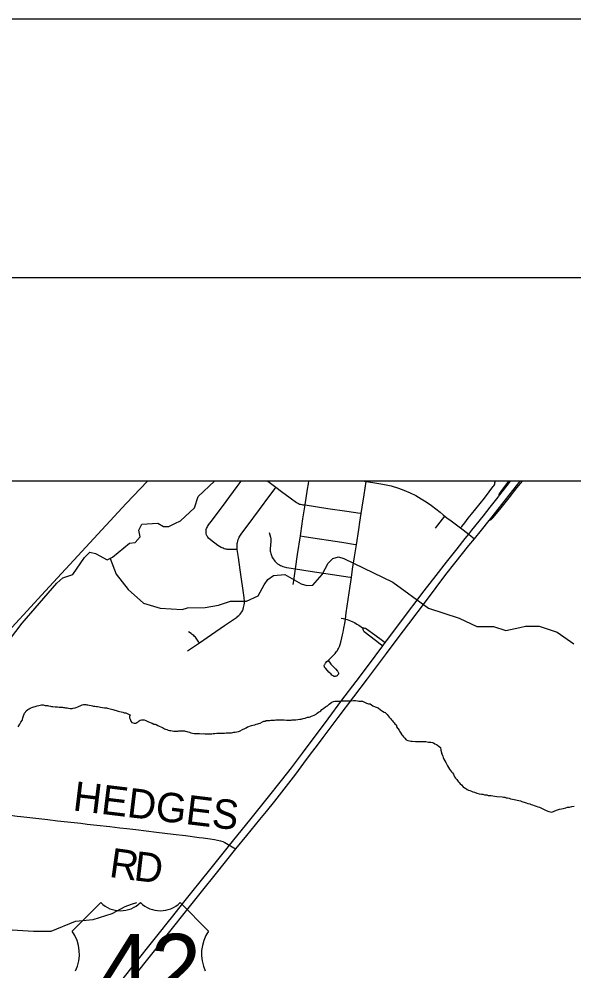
# Model space of a CAD drawing. Extents: x 0 to 34, y 0 to 22.
# Drawn here: x 11.27 to 12.342, y 20.159 to 22 of the extents above; entities that cross this region are included whole.
import ezdxf

# ---------------------------------------------------------------- set-up
doc = ezdxf.new("R2010")
doc.units = 0
for name, color, linetype in [('GM_X_City_Street', 7, 'Continuous'), ('GM_X_Corporation', 7, 'Continuous'), ('GM_X_Interchange_Ramps', 7, 'Continuous'), ('GM_X_Minor_River', 7, 'Continuous'), ('GM_X_Rail_Line', 7, 'Continuous'), ('GM_X_Township_Road', 7, 'Continuous'), ('GM_X_Township_Road_Text', 7, 'Continuous'), ('GM_X_US_Location', 7, 'Continuous'), ('GM_X_US_Route', 7, 'Continuous'), ('GM_X_US_Shield', 7, 'Continuous'), ('SH_Border', 7, 'Continuous'), ('SH_Cut_Line', 7, 'Continuous')]:
    doc.layers.add(name, color=color, linetype=linetype)

msp = doc.modelspace()

# ---------------------------------------------------------------- linework, layer by layer
at = {"layer": 'GM_X_City_Street'}
msp.add_line((12.0744, 21.0153), (12.0926, 21.0386), dxfattribs=at)
for points in [[(11.6914, 20.974), (11.6889, 20.974), (11.6833, 20.9739), (11.6754, 20.9738), (11.672, 20.9741), (11.6706, 20.9743), (11.6684, 20.9747), (11.6662, 20.9753), (11.6641, 20.9762), (11.6622, 20.977), (11.6602, 20.9779), (11.6573, 20.9795), (11.6538, 20.9816), (11.6395, 20.9925), (11.6358, 20.9959), (11.6345, 20.9974), (11.6336, 20.9988), (11.6328, 21.0003), (11.6319, 21.0022), (11.6314, 21.0046), (11.6312, 21.0065), (11.6311, 21.0083), (11.6313, 21.0104), (11.6315, 21.0126), (11.6321, 21.0147), (11.6329, 21.0165), (11.6338, 21.0182), (11.6354, 21.0206), (11.6379, 21.0241), (11.6416, 21.0288), (11.6699, 21.0665), (11.6913, 21.0955), (11.6991, 21.1059)], [(11.7505, 21.1059), (11.7555, 21.1021), (11.7661, 21.0942), (11.7769, 21.0861), (11.7935, 21.0741), (11.8061, 21.0648), (11.8082, 21.0636), (11.81, 21.0626), (11.812, 21.0618), (11.8139, 21.0613), (11.8164, 21.0609), (11.8183, 21.0605), (11.8225, 21.06), (11.8663, 21.0534), (11.9033, 21.0477), (11.9289, 21.0441), (11.9311, 21.0438)], [(11.7994, 20.9064), (11.7999, 20.9095), (11.8038, 20.9365), (11.8078, 20.9641), (11.8134, 21), (11.8141, 21.0046), (11.8184, 21.0329), (11.8225, 21.06), (11.8272, 21.0905), (11.8288, 21.101), (11.8299, 21.1059)], [(11.8668, 20.7591), (11.8695, 20.7558), (11.8725, 20.7523), (11.8811, 20.7433), (11.8851, 20.7385), (11.8858, 20.7375), (11.8864, 20.7364), (11.8868, 20.7355), (11.887, 20.7347), (11.8871, 20.7338), (11.8869, 20.7329), (11.8866, 20.7321), (11.8861, 20.7313), (11.8853, 20.7305), (11.8842, 20.7297), (11.883, 20.7291), (11.8819, 20.7287), (11.8808, 20.7284), (11.8798, 20.7284), (11.879, 20.7285), (11.8782, 20.7286), (11.8773, 20.729), (11.8765, 20.7294), (11.8755, 20.7301), (11.8745, 20.7309), (11.8728, 20.7326), (11.8686, 20.7368), (11.8656, 20.7397), (11.8619, 20.744), (11.8608, 20.7453), (11.8601, 20.7464), (11.8598, 20.7475), (11.8596, 20.7484), (11.8596, 20.7495), (11.8598, 20.7505), (11.8604, 20.7517), (11.861, 20.7527), (11.8617, 20.7538), (11.8647, 20.757), (11.8668, 20.7591), (11.8713, 20.7636), (11.8805, 20.7728), (11.8834, 20.7765), (11.885, 20.7787), (11.886, 20.7805), (11.887, 20.7826), (11.8887, 20.7865), (11.89, 20.7904), (11.8915, 20.7949), (11.8937, 20.8032), (11.895, 20.8088), (11.8962, 20.814), (11.8975, 20.8215), (11.8991, 20.8306), (11.9003, 20.8392), (11.9021, 20.8515), (11.9095, 20.9031), (11.9119, 20.9198), (11.9142, 20.9357), (11.9183, 20.9595), (11.9219, 20.9829), (11.9264, 21.0124), (11.9285, 21.0266), (11.9311, 21.0438), (11.9329, 21.056), (11.9365, 21.0799), (11.9403, 21.1055), (11.9404, 21.1059)], [(11.9372, 21.1059), (11.9403, 21.1055), (11.9532, 21.1036), (11.9728, 21.1003), (11.9892, 21.0967), (12.0028, 21.0927), (12.0133, 21.0888), (12.0253, 21.0836), (12.0364, 21.078), (12.0472, 21.0719), (12.0568, 21.0661), (12.0668, 21.0588), (12.0835, 21.0458), (12.0893, 21.0412), (12.0926, 21.0386), (12.0968, 21.0353), (12.1049, 21.029), (12.123, 21.0155)], [(11.5954, 20.7778), (11.6183, 20.7935), (11.6333, 20.8038), (11.6667, 20.8266), (11.6879, 20.8408), (11.6903, 20.8426), (11.6927, 20.8446), (11.6945, 20.8461), (11.6967, 20.8486), (11.6983, 20.8506), (11.7, 20.8531), (11.7012, 20.8551), (11.7026, 20.8582), (11.7037, 20.8616), (11.7044, 20.8643), (11.7049, 20.867), (11.7051, 20.8701), (11.7053, 20.8732), (11.7046, 20.8813), (11.6972, 20.9348), (11.6939, 20.9582), (11.6914, 20.974), (11.6909, 20.9804), (11.6909, 20.9827), (11.6912, 20.9854), (11.6917, 20.9876), (11.6923, 20.9902), (11.6932, 20.9932), (11.6942, 20.9955), (11.6952, 20.9979), (11.6964, 20.9999), (11.7001, 21.0056), (11.7104, 21.0193), (11.7341, 21.0513), (11.7546, 21.0786), (11.7645, 21.0921), (11.7661, 21.0942)], [(11.753, 21.0067), (11.7557, 20.9978), (11.7563, 20.9948), (11.7566, 20.9925), (11.7566, 20.9901), (11.7554, 20.9816), (11.7549, 20.9759), (11.755, 20.9736), (11.7552, 20.9708), (11.7556, 20.9685), (11.7561, 20.9664), (11.7567, 20.9643), (11.7575, 20.9622), (11.7585, 20.9598), (11.7598, 20.9576), (11.761, 20.9555), (11.7626, 20.9533), (11.7641, 20.9514), (11.7659, 20.9495), (11.7673, 20.948), (11.7692, 20.9464), (11.7707, 20.9452), (11.7729, 20.944), (11.7747, 20.9429), (11.7769, 20.942), (11.7794, 20.9411), (11.7823, 20.9402), (11.7866, 20.9392), (11.7909, 20.9384), (11.8038, 20.9365), (11.8321, 20.9321), (11.8623, 20.9277), (11.9096, 20.9202), (11.9119, 20.9198)], [(11.8134, 21), (11.821, 20.9988), (11.8504, 20.9944), (11.8675, 20.9918), (11.8933, 20.9879), (11.92, 20.9833), (11.9219, 20.9829)], [(11.8924, 20.8412), (11.8961, 20.8403), (11.9003, 20.8392), (11.9039, 20.8383), (11.9068, 20.8373), (11.9104, 20.8359), (11.9148, 20.8341), (11.918, 20.8324), (11.9226, 20.8296), (11.9261, 20.8273), (11.9334, 20.8224)], [(11.6183, 20.7935), (11.6174, 20.7948), (11.6132, 20.8007), (11.6118, 20.8024), (11.6105, 20.8042), (11.6089, 20.8058), (11.6073, 20.8074), (11.6044, 20.8095), (11.6023, 20.8112), (11.597, 20.8143)], [(11.9334, 20.8224), (11.9341, 20.8198), (11.9347, 20.8179), (11.9356, 20.8164), (11.9366, 20.8151), (11.9586, 20.7987), (11.9677, 20.7915), (11.9729, 20.7874)], [(11.9334, 20.8224), (11.9356, 20.8222), (11.9371, 20.822), (11.9392, 20.8214), (11.9412, 20.8205), (11.9571, 20.8086), (11.9721, 20.7976), (11.9776, 20.7937)]]:
    msp.add_lwpolyline(points, dxfattribs=at)
at = {"layer": 'GM_X_Corporation'}
msp.add_lwpolyline([(16.3375, 14.3932), (16.3375, 21.1059), (9.5375, 21.1059), (9.5375, 15.0426), (9.5452, 15.0418), (9.7185, 15.0258), (10.2502, 14.9799), (10.3112, 14.9746), (10.787, 14.9212), (11.3129, 14.8754), (11.3292, 14.8742), (12.1361, 14.7923), (13.6754, 14.6095), (14.714, 14.5341), (15.778, 14.4476), (16.0263, 14.4243)], close=True, dxfattribs=at)
msp.add_lwpolyline([(16.3375, 21.1059), (10.7333, 21.1059), (10.7324, 21.0977), (10.6961, 20.747), (10.69, 20.684), (10.7047, 20.6667), (10.7316, 20.6353), (10.7568, 20.6059), (10.7799, 20.5791), (10.8028, 20.5521), (10.8263, 20.5244), (10.8351, 20.5143), (10.841, 20.5074), (10.8449, 20.5034), (10.8495, 20.499), (10.8527, 20.4964), (10.8546, 20.4951), (10.8943, 20.447), (11.3101, 19.9435)], dxfattribs=at)
at = {"layer": 'GM_X_Interchange_Ramps'}
for points in [[(12.1783, 21.0301), (12.1807, 21.0313), (12.1821, 21.032), (12.1838, 21.0334), (12.1856, 21.0352), (12.1989, 21.0514), (12.2169, 21.0738), (12.2321, 21.093), (12.2425, 21.1059)], [(12.2159, 21.1059), (12.2008, 21.086), (12.1979, 21.0817), (12.197, 21.0797), (12.1967, 21.0784), (12.1963, 21.0762)]]:
    msp.add_lwpolyline(points, dxfattribs=at)
at = {"layer": 'GM_X_Minor_River'}
for points in [[(11.2514, 20.7988), (11.2759, 20.8311), (11.3425, 20.9089), (11.3544, 20.9193), (11.3735, 20.9255), (11.3961, 20.9585), (11.4062, 20.9686), (11.4175, 20.9661), (11.4397, 20.954), (11.4504, 20.9591), (11.4832, 20.9859), (11.4938, 20.9876), (11.5035, 20.9984), (11.5014, 21.011), (11.507, 21.0227), (11.5377, 21.0248), (11.5486, 21.0182), (11.5593, 21.0184), (11.5704, 21.0239), (11.5815, 21.029), (11.6089, 21.0547), (11.6161, 21.0766), (11.6476, 21.1059)], [(11.4455, 20.9567), (11.4571, 20.9259), (11.4805, 20.8967), (11.5104, 20.87), (11.5422, 20.8603), (11.585, 20.858), (11.5949, 20.8613), (11.6291, 20.8618), (11.655, 20.866), (11.6783, 20.8739), (11.7095, 20.8741), (11.7316, 20.884), (11.7434, 20.9058), (11.7504, 20.9156), (11.7612, 20.9238), (11.7836, 20.9253), (11.8152, 20.9073), (11.8258, 20.9041), (11.8372, 20.905), (11.8558, 20.9252), (11.8668, 20.9474), (11.8764, 20.9564), (11.8871, 20.9596), (11.8973, 20.9564), (11.9918, 20.9107), (12.0608, 20.8605), (12.1205, 20.8409), (12.1544, 20.8248), (12.1866, 20.8246), (12.2104, 20.817), (12.2379, 20.8229), (12.2486, 20.8254), (12.2747, 20.8254), (12.3099, 20.8137), (12.3418, 20.7912)], [(11.6019, 20.6194), (11.6083, 20.6178), (11.6118, 20.6178), (11.6148, 20.6177), (11.6167, 20.6177), (11.6186, 20.6177), (11.6227, 20.6173), (11.6258, 20.6177), (11.6288, 20.6172), (11.6326, 20.6172), (11.6356, 20.6172), (11.6375, 20.6172), (11.6398, 20.6172), (11.6421, 20.6171), (11.6447, 20.6179), (11.6481, 20.6182), (11.6516, 20.6186), (11.6554, 20.6185), (11.658, 20.6185), (11.6607, 20.6185), (11.6633, 20.6185), (11.6667, 20.6188), (11.6698, 20.6195), (11.6717, 20.6195), (11.6736, 20.6195), (11.6766, 20.6195), (11.68, 20.6195), (11.683, 20.6198), (11.6849, 20.6202), (11.6876, 20.6202), (11.6906, 20.6209), (11.694, 20.6216), (11.6959, 20.6224), (11.7028, 20.6261), (11.7047, 20.6268), (11.7085, 20.6291), (11.7112, 20.6306), (11.7138, 20.6317), (11.7169, 20.6328), (11.7188, 20.6332), (11.7218, 20.6343), (11.7256, 20.635), (11.7279, 20.6357), (11.7309, 20.6365), (11.7332, 20.6372), (11.7359, 20.6376), (11.7401, 20.6402), (11.7427, 20.6417), (11.7454, 20.642), (11.7473, 20.6428), (11.7499, 20.6428), (11.7537, 20.6431), (11.756, 20.6435), (11.7587, 20.6434), (11.7617, 20.6434), (11.7636, 20.6438), (11.7662, 20.6441), (11.7685, 20.6441), (11.7712, 20.6445), (11.7731, 20.6445), (11.775, 20.6441), (11.7772, 20.6444), (11.7799, 20.6444), (11.7822, 20.6444), (11.7867, 20.644), (11.7886, 20.6439), (11.792, 20.6439), (11.7958, 20.6439), (11.7977, 20.6442), (11.8007, 20.6442), (11.8045, 20.6446), (11.8087, 20.6449), (11.8125, 20.6456), (11.8148, 20.6456), (11.8186, 20.6467), (11.8224, 20.6478), (11.8269, 20.6493), (11.8303, 20.6497), (11.8326, 20.6504), (11.8349, 20.6515), (11.8368, 20.6519), (11.8398, 20.6534), (11.8437, 20.6556), (11.8456, 20.6575), (11.8486, 20.6594), (11.8509, 20.6605), (11.8532, 20.662), (11.8551, 20.6646), (11.8589, 20.6672), (11.862, 20.6695), (11.8639, 20.6706), (11.8661, 20.6717), (11.8692, 20.6747), (11.8719, 20.6766), (11.8745, 20.6785), (11.8772, 20.68), (11.8799, 20.6803), (11.8833, 20.6803), (11.8859, 20.6807), (11.8878, 20.6803), (11.8909, 20.6803)], [(11.8909, 20.6803), (11.8939, 20.681), (11.8965, 20.681), (11.8988, 20.6813), (11.9015, 20.6809), (11.906, 20.6813), (11.9117, 20.6812), (11.9163, 20.6815), (11.9197, 20.6815), (11.9235, 20.6811), (11.9261, 20.6807), (11.9299, 20.6803), (11.9333, 20.6803), (11.9412, 20.6768), (11.945, 20.6756), (11.9484, 20.6752), (11.9537, 20.6717), (11.9579, 20.6694), (11.9616, 20.6683), (11.9639, 20.6679), (11.968, 20.6636), (11.9722, 20.661), (11.9752, 20.659), (11.9771, 20.6583), (11.9794, 20.6563), (11.9809, 20.6544), (11.9831, 20.6521), (11.985, 20.6495), (11.9876, 20.6472), (11.9895, 20.6445), (11.9914, 20.6422), (11.9929, 20.6403), (11.9944, 20.6384), (11.9963, 20.6365), (11.9989, 20.6338), (11.9989, 20.6311), (12.0015, 20.6273), (12.0041, 20.6246), (12.0052, 20.6223), (12.0075, 20.6185), (12.0097, 20.6155), (12.0116, 20.6132), (12.0127, 20.6113), (12.015, 20.609), (12.018, 20.6059), (12.021, 20.6047), (12.0244, 20.6036), (12.0271, 20.6032), (12.0297, 20.6028), (12.0362, 20.6027), (12.0392, 20.6023), (12.0426, 20.6027), (12.0445, 20.6023), (12.0475, 20.6026), (12.0498, 20.6026), (12.0532, 20.6022), (12.0559, 20.6022), (12.0585, 20.6018), (12.0608, 20.6014), (12.0634, 20.6013), (12.0657, 20.6009), (12.0687, 20.6005), (12.071, 20.5998), (12.0736, 20.5982), (12.0763, 20.5967), (12.0785, 20.5951), (12.0816, 20.5928), (12.0842, 20.5909), (12.0849, 20.586), (12.086, 20.5814), (12.0864, 20.5795), (12.0875, 20.5772), (12.0886, 20.5738), (12.0894, 20.5715), (12.0908, 20.5681), (12.0946, 20.5616), (12.0964, 20.5582), (12.0976, 20.5555), (12.0998, 20.5524), (12.1017, 20.549), (12.1039, 20.5463), (12.1058, 20.5437), (12.1073, 20.5418), (12.1092, 20.5395), (12.1099, 20.5376), (12.1114, 20.5341), (12.1133, 20.5318), (12.1159, 20.5292), (12.1174, 20.5269), (12.1185, 20.525), (12.1204, 20.523), (12.1223, 20.5207), (12.1249, 20.5185), (12.1279, 20.5146), (12.1306, 20.5127), (12.1325, 20.5123), (12.1355, 20.5096), (12.1385, 20.5085), (12.1408, 20.5077), (12.1442, 20.5065), (12.1468, 20.5054)], [(11.2681, 20.631), (11.2708, 20.6363), (11.2731, 20.6401), (11.2754, 20.6431), (11.2765, 20.645), (11.2769, 20.648), (11.2785, 20.6518), (11.2796, 20.6552), (11.2804, 20.6571), (11.282, 20.659), (11.2831, 20.6616), (11.2865, 20.6646), (11.2892, 20.6657), (11.2911, 20.6672), (11.2942, 20.6683), (11.298, 20.6698), (11.301, 20.6702), (11.3044, 20.6717), (11.3078, 20.6724), (11.3105, 20.6728), (11.3131, 20.6731), (11.3162, 20.6731), (11.32, 20.6723), (11.3222, 20.6723), (11.3245, 20.6719), (11.3268, 20.6715), (11.3306, 20.6707), (11.3325, 20.6703), (11.3347, 20.6699), (11.3393, 20.6698), (11.3419, 20.6694), (11.3438, 20.6694), (11.3472, 20.669)], [(11.3472, 20.669), (11.3495, 20.6686), (11.3514, 20.6686), (11.3533, 20.6686), (11.3552, 20.6682), (11.3575, 20.6682), (11.3593, 20.6678), (11.3624, 20.6674), (11.365, 20.667), (11.3684, 20.6666), (11.3703, 20.6665), (11.3722, 20.6665), (11.3745, 20.6669), (11.3779, 20.6676), (11.3802, 20.6684), (11.3832, 20.6698), (11.3859, 20.671), (11.3878, 20.6713), (11.3916, 20.6736), (11.3939, 20.6739), (11.3958, 20.6743), (11.3988, 20.6739), (11.4007, 20.6735), (11.4026, 20.6731), (11.4052, 20.6727), (11.4087, 20.6723), (11.4113, 20.6715), (11.4136, 20.6711), (11.4162, 20.6707), (11.4193, 20.6703), (11.4215, 20.6699), (11.4242, 20.6695), (11.4272, 20.6691), (11.4348, 20.6679), (11.4367, 20.6679), (11.4386, 20.6675), (11.4408, 20.6671), (11.4431, 20.6663), (11.4457, 20.6655), (11.4484, 20.6647), (11.451, 20.6643), (11.4529, 20.6639), (11.4548, 20.6632), (11.4575, 20.6624), (11.4594, 20.662), (11.4613, 20.6612), (11.4635, 20.6608), (11.4669, 20.66), (11.4703, 20.6592), (11.473, 20.6581), (11.476, 20.6577), (11.4783, 20.6565), (11.4813, 20.6553), (11.4843, 20.6542), (11.4832, 20.6519), (11.4831, 20.6485), (11.4843, 20.6458), (11.4857, 20.642), (11.4876, 20.6393), (11.4918, 20.6378), (11.4937, 20.6378), (11.4956, 20.6378), (11.4975, 20.6393), (11.4998, 20.6408), (11.5017, 20.6423), (11.5036, 20.6434), (11.5066, 20.6441), (11.5093, 20.6445), (11.5115, 20.6444), (11.5149, 20.6429), (11.5187, 20.6413), (11.5229, 20.6394), (11.527, 20.6379), (11.53, 20.6363), (11.5327, 20.6359), (11.5346, 20.6351), (11.5376, 20.6336), (11.5402, 20.6324), (11.5467, 20.6297), (11.5485, 20.6282), (11.5508, 20.627), (11.5527, 20.6263), (11.5553, 20.6255), (11.5576, 20.6243), (11.5603, 20.6239), (11.5629, 20.6235), (11.5656, 20.6231), (11.5686, 20.6223), (11.5712, 20.6223), (11.5735, 20.6223), (11.5762, 20.6223), (11.5784, 20.623), (11.5811, 20.623), (11.5841, 20.6229), (11.5868, 20.6229), (11.5891, 20.6229), (11.5909, 20.6225), (11.5936, 20.6221), (11.5959, 20.6209), (11.5993, 20.6202), (11.6019, 20.6194)], [(12.1468, 20.5054), (12.1498, 20.5046), (12.1547, 20.5026), (12.1593, 20.5015), (12.1634, 20.5007), (12.1661, 20.5003), (12.1691, 20.4995), (12.1714, 20.4994), (12.1737, 20.4991), (12.1763, 20.4983), (12.1793, 20.4979), (12.1824, 20.4978), (12.1854, 20.4974), (12.1896, 20.497), (12.193, 20.4962), (12.2032, 20.4954), (12.2059, 20.495), (12.2085, 20.4946), (12.2112, 20.4938), (12.2138, 20.4934), (12.2168, 20.493), (12.2195, 20.4918), (12.2233, 20.491), (12.2267, 20.4902), (12.2297, 20.4898), (12.2323, 20.4887), (12.2354, 20.4883), (12.2388, 20.4875), (12.2414, 20.4867), (12.2437, 20.4859), (12.246, 20.4851), (12.2482, 20.4844), (12.2501, 20.4836), (12.2528, 20.4824), (12.2569, 20.4816), (12.2596, 20.4808), (12.2622, 20.4797), (12.2656, 20.4785), (12.269, 20.4773), (12.2724, 20.4762), (12.2754, 20.4754), (12.2781, 20.4742), (12.2807, 20.4727), (12.2845, 20.4708), (12.2887, 20.4688), (12.2939, 20.4673), (12.297, 20.4661), (12.2992, 20.4657), (12.3038, 20.4679), (12.3088, 20.4698), (12.3141, 20.4713), (12.3182, 20.4724), (12.3213, 20.4731), (12.3266, 20.4742), (12.33, 20.4753), (12.3338, 20.4756), (12.3384, 20.4764), (12.3425, 20.4771)], [(10.8028, 20.2783), (10.813, 20.2773), (10.8242, 20.265), (10.8364, 20.2432), (10.8446, 20.2335), (10.8543, 20.2277), (10.8892, 20.2206), (10.9148, 20.2095), (10.9481, 20.2029), (10.9941, 20.2044), (11.083, 20.2336), (11.1223, 20.2428), (11.1834, 20.2425), (11.2976, 20.2353), (11.3314, 20.2354), (11.3788, 20.2551), (11.413, 20.2583), (11.4493, 20.2695), (11.4746, 20.2835), (11.4872, 20.2878), (11.4971, 20.2907)]]:
    msp.add_lwpolyline(points, dxfattribs=at)
at = {"layer": 'GM_X_Rail_Line'}
msp.add_lwpolyline([(9.5375, 18.9204), (9.5733, 18.957), (9.6203, 19.0043), (9.9312, 19.2901), (10.181, 19.5285), (10.2632, 19.6118), (10.3245, 19.6797), (10.3809, 19.7534), (10.467, 19.8683), (10.5914, 20.0425), (10.8, 20.3326), (10.8632, 20.411), (10.9292, 20.4905), (11.0258, 20.5881), (11.2265, 20.7922), (11.3209, 20.8938), (11.4765, 21.063), (11.518, 21.1059)], dxfattribs=at)
at = {"layer": 'GM_X_Township_Road'}
msp.add_line((12.123, 21.0155), (12.1389, 21.0033), dxfattribs=at)
for points in [[(12.1744, 21.0801), (12.1749, 21.0809), (12.1817, 21.0898), (12.1861, 21.0957), (12.1873, 21.0973), (12.1884, 21.0992), (12.189, 21.1009), (12.1896, 21.1027), (12.1901, 21.1045), (12.1904, 21.1059)], [(12.123, 21.0155), (12.1252, 21.0182), (12.1311, 21.0256), (12.138, 21.0346), (12.1442, 21.0425), (12.1523, 21.0527), (12.1691, 21.073), (12.1744, 21.0801)], [(12.1389, 21.0033), (12.1433, 20.9999), (12.1499, 20.9948)], [(11.1102, 20.475), (11.1198, 20.4747), (11.131, 20.4738), (11.1402, 20.4727), (11.2006, 20.4657), (11.2221, 20.4634), (11.2486, 20.4603), (11.2659, 20.4582), (11.2731, 20.4573)], [(11.2731, 20.4573), (11.296, 20.4546), (11.3139, 20.4526), (11.325, 20.4513), (11.3436, 20.4492)], [(11.3436, 20.4492), (11.3567, 20.4478), (11.3889, 20.4443), (11.4012, 20.4427), (11.4197, 20.4406), (11.445, 20.4378), (11.4647, 20.4353), (11.4777, 20.4339), (11.4956, 20.432), (11.5351, 20.4271), (11.5672, 20.4232), (11.5912, 20.4204), (11.6177, 20.417), (11.6257, 20.416), (11.6387, 20.4144), (11.6474, 20.4131), (11.6535, 20.4119), (11.659, 20.4105), (11.6637, 20.4088), (11.6672, 20.4071), (11.674, 20.4034), (11.6764, 20.4019)], [(11.6764, 20.4019), (11.6786, 20.4007), (11.6847, 20.397), (11.6884, 20.3946)]]:
    msp.add_lwpolyline(points, dxfattribs=at)
at = {"layer": 'GM_X_US_Route'}
for p, q in [((11.9729, 20.7874), (11.9776, 20.7937)), ((11.6484, 20.3444), (11.6884, 20.3946))]:
    msp.add_line(p, q, dxfattribs=at)
for points in [[(12.1673, 21.0393), (12.1803, 21.0559), (12.1957, 21.0754), (12.1963, 21.0762), (12.2134, 21.0979), (12.2198, 21.1059)], [(12.1783, 21.0301), (12.1815, 21.0341), (12.2239, 21.0877), (12.2383, 21.1059)], [(11.6884, 20.3946), (11.7102, 20.4208), (11.7348, 20.4513), (11.7477, 20.4672), (11.7637, 20.487), (11.7868, 20.5163), (11.8045, 20.5395), (11.8202, 20.5603), (11.8332, 20.5777), (11.8463, 20.5951), (11.8575, 20.61), (11.8866, 20.6488), (11.9169, 20.689), (11.9431, 20.7237), (11.98, 20.7729), (12.0024, 20.8027), (12.0229, 20.8301), (12.0569, 20.8752), (12.0948, 20.9253), (12.1121, 20.9472), (12.1392, 20.9813), (12.1499, 20.9948), (12.1632, 21.0113), (12.1783, 21.0301)], [(11.9776, 20.7937), (11.9826, 20.8004), (12.0072, 20.8332), (12.0528, 20.8938), (12.0758, 20.9238), (12.0957, 20.9493), (12.1162, 20.9751), (12.1322, 20.9949), (12.1389, 21.0033), (12.1449, 21.011), (12.1673, 21.0393)], [(11.6764, 20.4019), (11.7154, 20.45), (11.7492, 20.4921), (11.7767, 20.5267), (11.7961, 20.5518), (11.8173, 20.5802), (11.8669, 20.6463), (11.8938, 20.6821), (11.921, 20.7184), (11.9431, 20.7476), (11.9729, 20.7874)], [(11.3104, 19.943), (11.3184, 19.9531), (11.3346, 19.9735), (11.3564, 20.0006), (11.3911, 20.0437), (11.4127, 20.071), (11.4395, 20.1044), (11.4593, 20.1292), (11.4929, 20.1716), (11.5305, 20.2195), (11.5434, 20.2353), (11.556, 20.2508), (11.5668, 20.2644), (11.5857, 20.2883), (11.6063, 20.314), (11.6199, 20.3309), (11.6408, 20.3572), (11.6719, 20.3962), (11.6764, 20.4019)], [(11.2819, 19.8844), (11.3022, 19.9097), (11.3297, 19.9442), (11.3639, 19.9869), (11.3915, 20.0213), (11.4321, 20.0724), (11.4649, 20.1137), (11.4885, 20.1434), (11.5287, 20.194), (11.5562, 20.2285), (11.5993, 20.2824), (11.6247, 20.3146), (11.6484, 20.3444)]]:
    msp.add_lwpolyline(points, dxfattribs=at)
at = {"layer": 'GM_X_US_Shield'}
for p, q in [((11.4274, 20.2907), (11.3724, 20.2357)), ((11.6361, 20.2357), (11.5812, 20.2907))]:
    msp.add_line(p, q, dxfattribs=at)
for centre, radius, start, end in [((11.4658, 20.3299), 0.0549, 225.573, 314.427), ((11.5427, 20.3299), 0.0549, 225.573, 314.427), ((11.3094, 20.1916), 0.0769, 334.5471, 35.0009), ((11.6991, 20.1916), 0.0769, 144.9991, 205.4529)]:
    msp.add_arc(centre, radius, start, end, dxfattribs=at)
at = {"layer": 'SH_Border'}
msp.add_lwpolyline([(1.5, 21.5), (33.5, 21.5), (33.5, 0.5), (1.5, 0.5)], close=True, dxfattribs=at)
at = {"layer": 'SH_Cut_Line'}
msp.add_lwpolyline([(0, 0), (34, 0), (34, 22), (0, 22)], close=True, dxfattribs=at)

# ---------------------------------------------------------------- texts
at = {"layer": 'GM_X_Township_Road_Text'}
for s, height, rotation, p in [('HEDGES', 0.05682, 353.1096, (11.372, 20.4693)), ('R', 0.0568, 351.8782, (11.4422, 20.3408)), ('D', 0.0568, 353.2021, (11.4898, 20.3341))]:
    msp.add_text(s, height=height, rotation=rotation, dxfattribs=at).set_placement(p)
at = {"layer": 'GM_X_US_Location'}
for s in ['0', '/']:
    msp.add_text(s, height=0.000189, dxfattribs=at).set_placement((11.5042, 20.1633))
at = {"layer": 'GM_X_US_Shield'}
msp.add_text('42', height=0.13184, dxfattribs=at).set_placement((11.4255, 20.0984))

doc.saveas('drawing.dxf')
